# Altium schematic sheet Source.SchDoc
size B; SheetNumber: 1; SheetTotal: 2
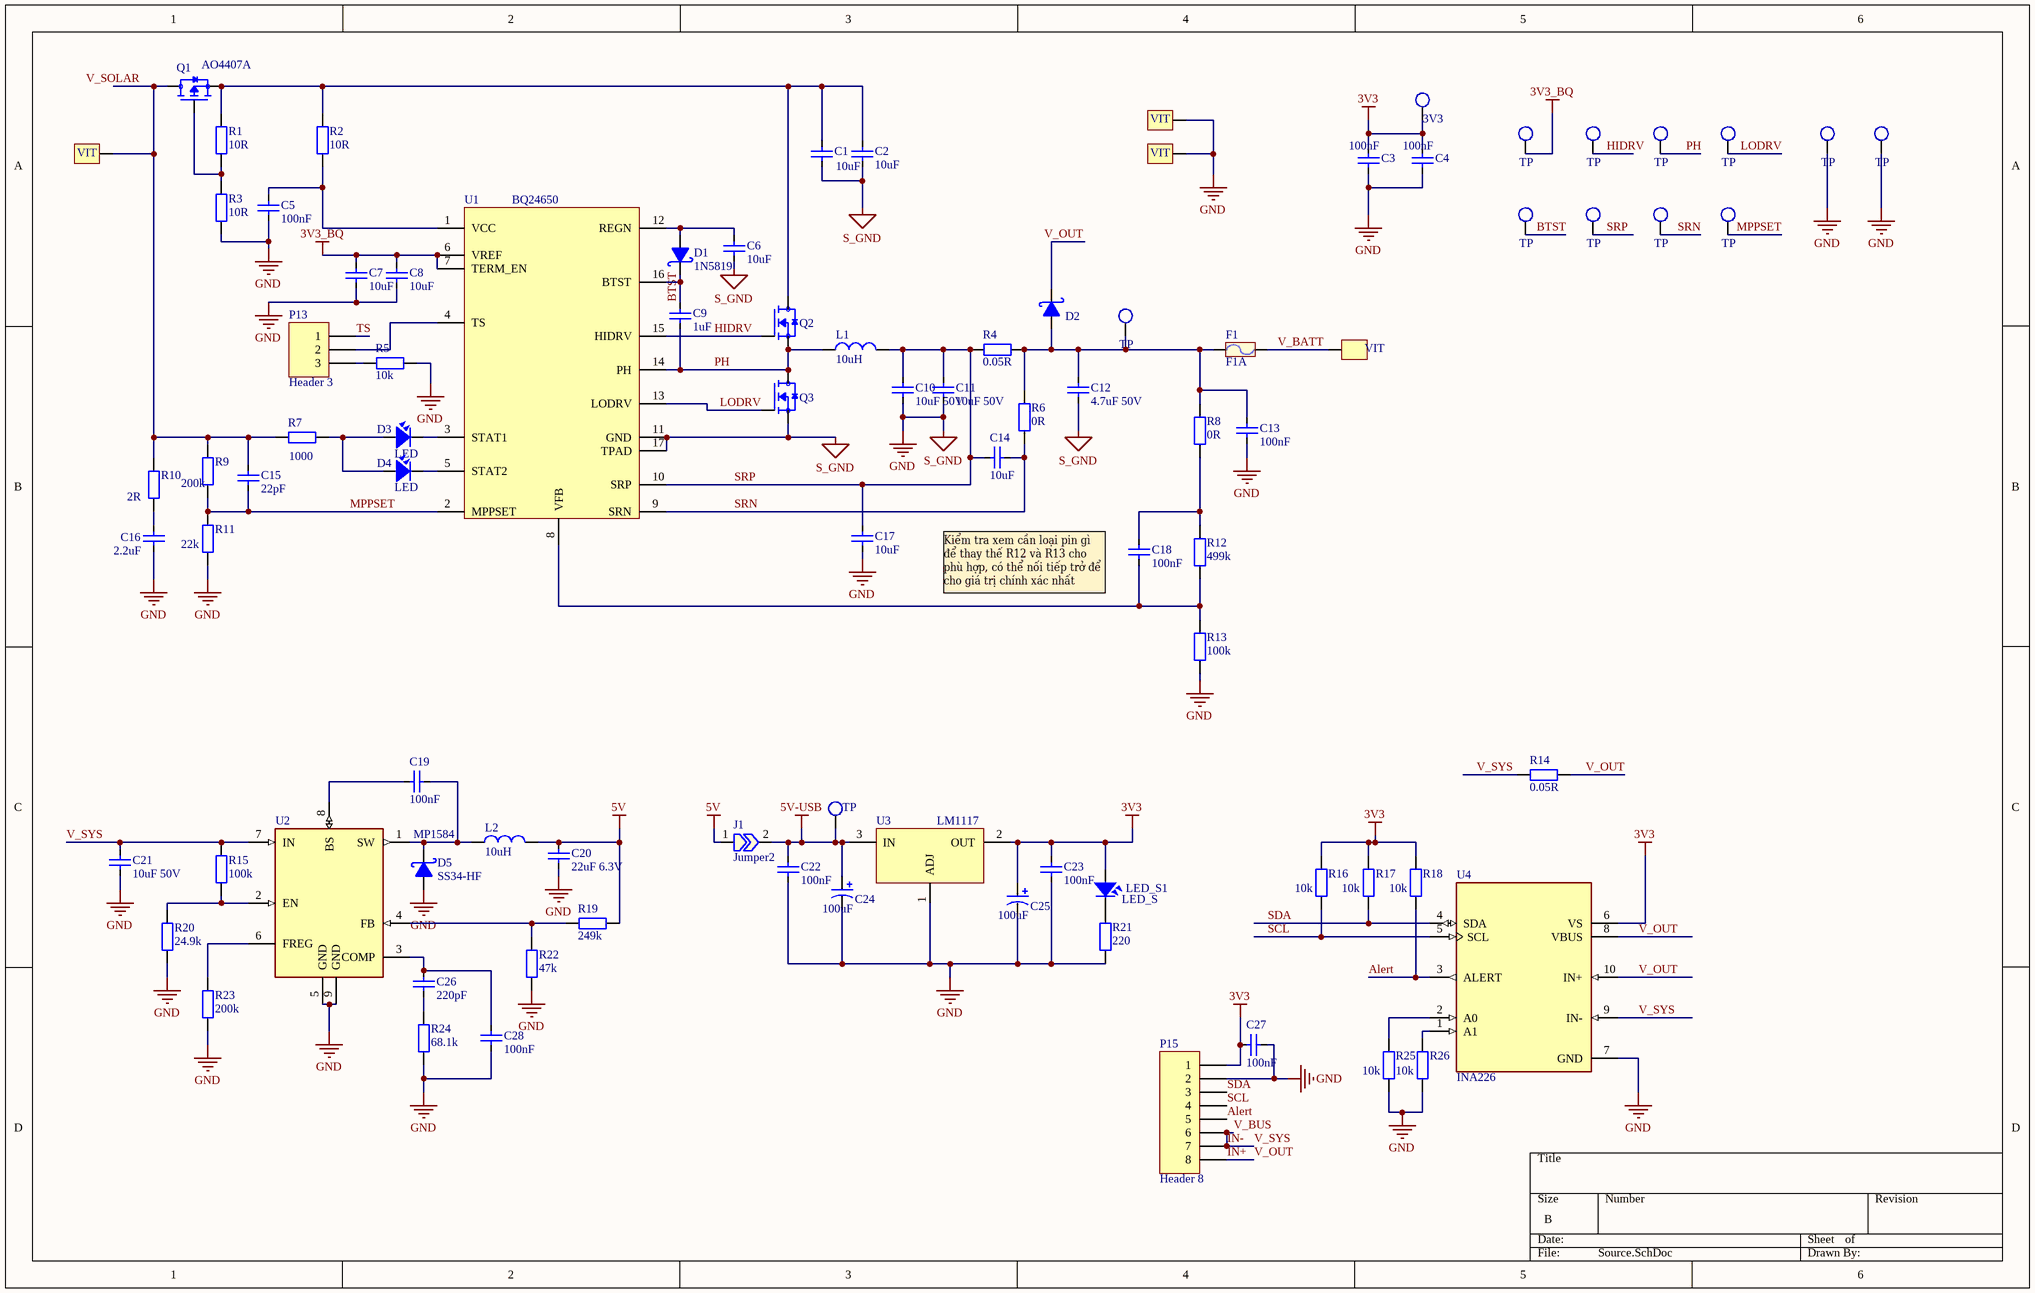
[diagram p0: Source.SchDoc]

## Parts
C1  10uF  [CAP_3216]
C2  10uF  [CAP_3216]
C3  100nF  [CAP_0805]
C4  100nF  [CAP_0805]
C5  100nF  [CAP_0805]
C6  10uF  [CAP_0805]
C7  10uF  [CAP_0805]
C8  10uF  [CAP_0805]
C9  1uF  [CAP_0805]
C10  10uF 50V  [CAP_1206]
C11  10uF 50V  [CAP_1206]
C12  4.7uF 50V  [CAP_1206]
C13  100nF  [CAP_0805]
C14  10uF  [CAP_0805]
C15  22pF  [CAP_0805]
C16  2.2uF  [CAP_0805]
C17  10uF  [CAP_0805]
C18  100nF  [CAP_0805]
C19  100nF  [CAP_0805]
C20  22uF 6.3V  [CAP_0805]
C21  10uF 50V  [CAP_3216]
C22  100nF  [CAP_0805]
C23  100nF  [CAP_0805]
C24  100uF  [CAP_7343]
C25  100uF  [CAP_7343]
C26  220pF  [CAP_0805]
C27  100nF  [CAP_0805]
C28  100nF  [CAP_0805]
D1  1N5819  [DIO-SMD-123]
D2  Diode Schottky  [DIO-214AA(SMB)]  (value not drawn)
D3  LED  [LED-0805-Green]
D4  LED  [LED-0805-Red]
D5  SS34-HF  [SMA]
F1  F1A  [RES-SMD-1812]
J1  Jumper2  [RES-SMD-0402]  (no BOM)
L1  10uH  [L-SMD-M-12x10]
L2  10uH  [L-SMD-M-7.3x4.5]
LED_S1  LED_S  [LED-0805-Blue]
P1  3V3  [Testpoint 50ml]  (no BOM)
P2  TP  [Testpoint 50ml]  (no BOM)
P3  TP  [Testpoint 50ml]  (no BOM)
P4  TP  [Testpoint 50ml]  (no BOM)
P5  TP  [Testpoint 50ml]  (no BOM)
P6  TP  [Testpoint 50ml]  (no BOM)
P7  TP  [Testpoint 50ml]  (no BOM)
P8  TP  [Testpoint 50ml]  (no BOM)
P9  TP  [Testpoint 50ml]  (no BOM)
P10  TP  [Testpoint 50ml]  (no BOM)
P11  TP  [Testpoint 50ml]  (no BOM)
P12  TP  [Testpoint 50ml]  (no BOM)
P13  Header 3  [HDR1X3]  (no BOM)
P14  TP  [Testpoint 50ml]  (no BOM)
P15  Header 8  [HDR1X8]  (no BOM)
Q1  AO4407A  [SOIC-8]
Q2  AON6508  [MOSFET_HP_8Pin]  (value not drawn)
Q3  AON6508  [MOSFET_HP_8Pin]  (value not drawn)
R1  10R  [RES-SMD-0805]
R2  10R  [RES-SMD-0805]
R3  10R  [RES-SMD-0805]
R4  0.05R  [RES-SMD-2512]
R5  10k  [RES-SMD-0805]
R6  0R  [RES-SMD-0805]
R7  1000  [RES-SMD-0805]
R8  0R  [RES-SMD-0805]
R9  200k  [RES-SMD-0805]
R10  2R  [RES-SMD-2512]
R11  22k  [RES-SMD-0805]
R12  499k  [RES-SMD-0805]
R13  100k  [RES-SMD-0805]
R14  0.05R  [RES-SMD-2512]
R15  100k  [RES-SMD-0805]
R16  10k  [RES-SMD-0805]
R17  10k  [RES-SMD-0805]
R18  10k  [RES-SMD-0805]
R19  249k  [RES-SMD-0805]
R20  24.9k  [RES-SMD-0805]
R21  220  [RES-SMD-0805]
R22  47k  [RES-SMD-0805]
R23  200k  [RES-SMD-0805]
R24  68.1k  [RES-SMD-0805]
R25  10k  [RES-SMD-0805]
R26  10k  [RES-SMD-0805]
U1  BQ24650  [VQFN-16]
U2  MP1584  [SOP8-PP]
U3  LM1117  [SOT-223]
U4  INA226  [VSSOP-10]
VIT1  1  [VIT]  (value not drawn)  (no BOM)
VIT2  1  [VIT]  (value not drawn)  (no BOM)
VIT3  1  [VIT]  (value not drawn)  (no BOM)
VIT4  1  [VIT]  (value not drawn)  (no BOM)

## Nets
3V3: C3.2 C4.2 C23.2 C25.1 C27.2 LED_S1.1 P1.1 P15.1 R16.1 R17.1 R18.1 U3.2(OUT) U4.6(VS)
3V3_BQ: C7.2 C8.2 P2.1 U1.6(VREF) U1.7(TERM_EN)
5V: C20.2 J1.1 L2.2 R19.1
5V-USB: C22.2 C24.1 J1.2 P14.1 U3.3(IN)
GND: C1.1 C2.1 C3.1 C4.1 C5.1 C6.1 C7.1 C8.1 C10.1 C11.1 C12.2 C13.1 C16.1 C17.1 C20.1 C21.1 C22.1 C23.1 C24.2 C25.2 C27.1 C28.1 D5.1(A) P6.1 P7.1 P15.2 Q3.1,2,3(S) R3.2 R5.2 R11.2 R13.2 R20.2 R21.2 R22.2 R23.2 R24.2 R25.2 R26.2 U1.11(GND) U1.17(TPAD) U2.5(GND) U2.9(GND) U3.1(ADJ) U4.7(GND) VIT1.VIT1 VIT3.VIT1  [also labelled S_GND]
Alert: P15.5 R18.2 U4.3(ALERT)
BTST: C9.2 D1.2(K) P8.1 U1.16(BTST)
HIDRV: P3.1 Q2.4(G) U1.15(HIDRV)
IN+: D2.2(K) P15.8 R14.1 U4.8(VBUS) U4.10(IN+)  [also labelled V_OUT]
IN-: C21.2 P15.6 P15.7 R14.2 R15.1 U2.7(IN) U4.9(IN-)  [also labelled V_BUS, V_SYS]
LODRV: P5.1 Q3.4(G) U1.13(LODRV)
MPPSET: C15.1 P11.1 R9.2 R11.1 U1.2(MPPSET)
PH: C9.1 L1.1 P4.1 Q2.1,2,3(S) Q3.5,6,7,8,9(D) U1.14(PH)
SCL: P15.4 R16.2 U4.5(SCL)
SDA: P15.3 R17.2 U4.4(SDA)
SRN: C14.1 P10.1 R6.2 U1.9(SRN)
SRP: C10.2 C11.2 C14.2 C17.2 L1.2 P9.1 R4.2 U1.10(SRP)
TS: P13.1
V_BATT: F1.2 VIT4.VIT1
V_SOLAR: C15.2 Q1.5,_6,_7,_8(D) R7.2 R9.1 R10.1 VIT2.VIT1
NetC1_2: C1.2 C2.2 Q1.1,_2,_3(S) Q2.5,6,7,8,9(D) R1.1 R2.1
NetC5_2: C5.2 R2.2 U1.1(VCC)
NetC6_2: C6.2 D1.1(A) U1.12(REGN)
NetC12_1: C12.1 C13.2 D2.1(A) F1.1 P12.1 R4.1 R6.1 R8.1
NetC16_2: C16.2 R10.2
NetC18_1: C18.1 R12.2 R13.1 U1.8(VFB)
NetC18_2: C18.2 R8.2 R12.1
NetC19_1: C19.1 U2.8(BS)
NetC19_2: C19.2 D5.2(K) L2.1 U2.1(SW)
NetC26_1: C26.1 R24.1
NetC26_2: C26.2 C28.2 U2.3(COMP)
NetD3_1: D3.1 D4.1 R7.1
NetD3_2: D3.2 U1.3(STAT1)
NetD4_2: D4.2 U1.5(STAT2)
NetLED_S1_2: LED_S1.2 R21.1
NetP13_2: P13.2 U1.4(TS)
NetP13_3: P13.3 R5.1
NetQ1_4: Q1.4(G) R1.2 R3.1
NetR15_2: R15.2 R20.1 U2.2(EN)
NetR19_2: R19.2 R22.1 U2.4(FB)
NetR23_1: R23.1 U2.6(FREG)
NetR25_1: R25.1 U4.2(A0)
NetR26_1: R26.1 U4.1(A1)

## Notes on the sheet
- (near C18) Kiểm tra xem cần loại pin gì để thay thế R12 và R13 cho phù hợp, có thể nối tiếp trở để cho giá trị chính xác nhất

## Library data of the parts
C1 C2 = CapSMD: C 3216; Value: 33p
C3-C9 C13-C20 C22 C23 C26-C28 = CapSMD: C 0805; Value: 33p
C10-C12 C21 = CapSMD: C 1206; Value: 33p
C24 C25 = CAP_TAN_SMD: C Tan 7343
D1 D5 = 1N5822: Schottky Rectifiers; Value: Diode c?m 1N5408
D2 = Diode Schottky: SS54
D3 D4 LED_S1 = LED: LED Single colour Green and Red; Value: LED 3 ly Single Colour
F1 = Fuse: Fuse 5A; Designed by: VanDungEvn
J1 = Jumper2: Jumper, 2-Pin
L1 = Inductor: Value: 150 mH
L2 = Inductor: 6.8-10uH; Value: 150 mH
P1-P12 P14 = TP_1: Test Point
P13 = Header 3: Header, 3-Pin
P15 = Header 8: Header, 8-Pin
Q1 = MOSFET-P: MFET-ChP
Q2 Q3 = MOSFET-N: MFET-CHP
R1-R3 R5-R7 R15-R18 R21 R23-R26 = Resistor - SMD: R 0805; Manufacturer: Generic Components; Class: Passive
R4 R14 = Resistor - SMD: R 2512 1%; Manufacturer: Generic Components; Class: Passive
R8 R9 R11-R13 R19 R20 R22 = Resistor - SMD: R 0805 1%; Manufacturer: Generic Components; Class: Passive
R10 = Resistor - SMD: R 2512; Manufacturer: Generic Components; Class: Passive
U1 = BQ24650: BQ24650 Stand-Alone Synchronous Buck Battery Charge Controller for Solar Power / With Maximum Power Point Tracking
U2 = MP1584: MP1584, The wide 4.5V to 28V input range accommodates a   variety   of   step-down   applications, SOIC8E
U3 = LM1117: 3V3 5V LDO, AMS1117, LDI1117
U4 = INA226: Current Sensing IC
VIT1-VIT4 = VIT: Oc Vit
